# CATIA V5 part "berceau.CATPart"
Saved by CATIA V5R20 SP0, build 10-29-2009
Part number: berceau
Bounding box of the stored display mesh (mm): x -325 to 325, y -1050 to -50, z 1210.026 to 1425
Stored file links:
  D:\Dropbox\Pack 1 sylvain\mmoreau\mmoreau\mmoreau\fin\berceau.CATPart
  U:\think motion\fin\think motion2.CATProduct
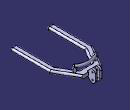
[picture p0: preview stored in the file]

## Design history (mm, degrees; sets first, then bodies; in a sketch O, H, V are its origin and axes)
External parameters (linked from other documents)
  `External.largeur levier` = 40 mm
Set1
  Plane1: linked copy from another document
  Plane2: linked copy from another document
  Point1: linked copy from another document
  Plane3: linked copy from another document
  Point2: linked copy from another document
Set2
  Plane4: type Normal, Curve Sketch3, RefPoint Sketch3.P2
  Plane5: type Normal, Curve Sketch5, RefPoint Sketch5.P2
Body1 (main body)
  Sketch1 on Plane1, origin (0, 0, 1300), H (1, 0, 0), V (0, 1, 0)
    line L1 (-150, -150) -> (150, -150)
    line L2 (325, -453.1089) -> (325, -1050)
    line L3 (-225, -1050) -> (-325, -1050)
    line L4 (-325, -1050) -> (-325, -453.1089)
    point P1 (-325, -1050)
    line L5 (150, -150) -> (325, -453.1089)
    point P3 (325, -453.1089)
    point P4 (-325, -453.1089)
    line L6 (-150, -150) -> (-325, -453.1089)
    line L7 (-225, -1050) -> (-225, -479.9038)
    point P6 (-225, -1050)
    point P7 (-225, -479.9038)
    line L8 (-225, -479.9038) -> (-92.265, -250)
    point P8 (-92.265, -250)
    line L9 (-92.265, -250) -> (0, -250)
    point P9 (-92.265, -250)
    point P10 (0, -250)
    point P11 (225, -479.9038)
    point P12 (225, -1050)
    line L10 (225, -1050) -> (225, -479.9038)
    point P13 (92.265, -250)
    line L11 (225, -479.9038) -> (92.265, -250)
    point P14 (0, -250)
    point P15 (92.265, -250)
    line L12 (92.265, -250) -> (0, -250)
    point P16 (325, -1050)
    line L13 (225, -1050) -> (325, -1050)
    reference intersected line E1 through (0, -150) direction (1, 0) from Plane3
    distance L2 L4 = 650
    distance L7 L4 = 100
    distance L8 L6 = 100
    distance L9 L1 = 100
    angle L6 L1 = 120
    length L1 = 300
    distance L3 L9 = 800
    horizontal: L1 H, L3 H, L9 H
    vertical: L2 V, L4 V, L7 V
    symmetry: L4 L2 V, P3 P4 V, L5 L6 V, P7 P11 V, P6 P12 V, L7 L10 V, P8 P13 V, L8 L11 V, P10 P14 V, P9 P15 V, L9 L12 V, P1 P16 V, L3 L13 V
    coincidence: P9 L8, P10 V, P8 P9, E1 L1
  Pad1: profile Sketch1, direction (0, 0, 1), length 25, mirrored extent
  Sketch2 on Plane4, origin (224.3751, -208.243, 0), H (-0.6803, -0.733, 0), V (0, 0, 1)
    line L1 (59.8343, 1425) -> (99.8343, 1425)
    line L2 (99.8343, 1425) -> (99.8343, 1325)
    line L3 (99.8343, 1325) -> (59.8343, 1325)
    line L4 (59.8343, 1325) -> (59.8343, 1425)
    point P4 (59.8343, 1325)
    reference projected point E1 (59.8343, 1325) from Sketch3.P2
    distance L2 L4 = 40
    distance L3 L1 = 100
    horizontal: L1 H, L3 H
    vertical: L2 V, L4 V
    coincidence: P4 E1
  Sketch3 on end face of Pad1, origin (0, 0, 1325), H (1, 0, 0), V (0, 1, 0)
    arc A1 centre (0, -450) radius 270 from (183.6719, -252.0994) to (-183.6719, -252.0994) ccw
    point P1 (0, -450)
    point P2 (183.6719, -252.0994)
    point P3 (-183.6719, -252.0994)
    reference projected point E1 (0, -150) from Point2
    distance P2 P3 V = 0
    radius A1 = 270
    distance E1 P1 = 300
    coincidence: P1 V
  Rib1: profile Sketch2, centre curve Sketch3
  Fillet1: radius 20, on edge [face of Rib1 | face of Rib1] (x6)
  Fillet2: radius 20, on edge [face of Fillet1 | face of Fillet1] (x2)
  Sketch4 on Plane5, origin (210.6842, -141.9392, 0), H (-0.5645, -0.8254, 0), V (0, 0, 1)
    line L1 (103.2148, 1385) -> (143.2148, 1385)
    line L2 (143.2148, 1385) -> (143.2148, 1325)
    line L3 (143.2148, 1325) -> (103.2148, 1325)
    line L4 (103.2148, 1325) -> (103.2148, 1385)
    point P4 (103.2148, 1325)
    reference projected point E1 (103.2148, 1325) from Sketch5.P2
    distance L4 L2 = 40
    distance L3 L1 = 60
    horizontal: L1 H, L3 H
    vertical: L2 V, L4 V
    coincidence: P4 E1
  Sketch5 on end face of Pad1, origin (0, 0, 1325), H (1, 0, 0), V (0, 1, 0)
    arc A1 centre (0, -450) radius 270 from (152.4182, -227.1353) to (-152.4182, -227.1353) ccw
    point P1 (0, -450)
    point P2 (152.4182, -227.1353)
    point P3 (-152.4182, -227.1353)
    reference projected arc E1 centre (0, -450) radius 270 from (183.6719, -252.0994) to (-183.6719, -252.0994) ccw from Sketch3.A1
    reference projected arc E2 centre (0, -450) radius 270 from (183.6719, -252.0994) to (-183.6719, -252.0994) ccw from Sketch3.A1
    reference projected point E3 (183.6719, -252.0994) from vertex [element of Sketch2 | element of Sketch2]
    distance P2 P3 V = 0
    distance E3 P2 = 40
    coincidence: P1 V, A1 E2
    concentricity: A1 E1
  Slot1: profile Sketch4, centre curve Sketch5
  Fillet3: radius 20, on edge [face of Slot1 | face of Rib1]; edge [face of Rib1 | face of Slot1]
  Fillet4: radius 18, on edge [face of Rib1 | face of Slot1] (x4)
  Fillet5: radius 18, on edge [face of Slot1 | face of Fillet3] (x2)
  Fillet6: radius 25, on edge [face of Pad1 from Sketch1.L10 | face of Slot1]; edge [start face of Pad1 | face of Pad1 from Sketch1.L10]; edge [face of Pad1 from Sketch1.L11 | face of Slot1]; edge [face of Pad1 from Sketch1.L8 | face of Slot1]; edge [face of Pad1 from Sketch1.L7 | face of Slot1]; edge [start face of Pad1 | face of Pad1 from Sketch1.L11]; edge [start face of Pad1 | face of Pad1 from Sketch1.L12]; edge [start face of Pad1 | face of Pad1 from Sketch1.L8]; edge [start face of Pad1 | face of Pad1 from Sketch1.L7]; edge [face of Pad1 from Sketch1.L12 | face of Slot1]; edge [face of Pad1 from Sketch1.L2 | face of Slot1]; edge [start face of Pad1 | face of Pad1 from Sketch1.L2]; edge [face of Pad1 from Sketch1.L5 | face of Slot1]; edge [start face of Pad1 | face of Pad1 from Sketch1.L5]; edge [face of Pad1 from Sketch1.L4 | face of Slot1]; edge [start face of Pad1 | face of Pad1 from Sketch1.L4]; edge [face of Pad1 from Sketch1.L6 | face of Slot1]; edge [start face of Pad1 | face of Pad1 from Sketch1.L6]
  Fillet7: radius 25, on face of Pad1 from Sketch1.L13; face of Pad1 from Sketch1.L3
  Sketch6 on Plane2, origin (0, 0, 0), H (0, 1, 0), V (0, 0, 1)
    line L1 (-171.5685, 1325) -> (-118.2843, 1378.2843)
    point P1 (-171.5685, 1325)
    point P2 (-50, 1446.5685)
    line L2 (-50, 1350) -> (-50, 1250)
    point P3 (-50, 1446.5685)
    point P4 (-50, 1153.4315)
    line L3 (-118.2843, 1221.7157) -> (-171.5685, 1275)
    point P5 (-171.5685, 1275)
    reference projected line E1 (-150, 1325) -> (-459.8076, 1325) from edge [face of Fillet6 | face of Slot1]
    reference projected line E2 (-459.8076, 1275) -> (-150, 1275) from edge [start face of Pad1 | face of Fillet6]
    reference projected line E3 (-453.1089, 1300) -> (-150, 1300) from edge [face of Fillet6 | face of Fillet6]
    arc A1 centre (-90, 1350) radius 40 from (-118.2843, 1378.2843) to (-50, 1350) cw
    point P8 (-90, 1350)
    arc A2 centre (-90, 1250) radius 40 from (-118.2843, 1221.7157) to (-50, 1250) ccw
    line L4 (-171.5685, 1325) -> (-171.5685, 1275)
    point P12 (-171.5685, 1275)
    circle A3 centre (-90, 1350) radius 10
    point P13 (-90, 1350)
    circle A4 centre (-90, 1250) radius 10
    reference projected point E4 (-90, 1350) from Point1
    distance P5 P1 H = 0
    radius A1 = 40
    radius A2 = 40
    radius A3 = 10
    radius A4 = 10
    coincidence: P3 L1, P2 P3, P1 E1, P5 E2, L1 P2, L2 P3, L3 P4, L2 P4, P12 L3, P13 P8, P12 P5, E4 P13
    vertical: L2 V
    perpendicularity: L3 L1
    symmetry: P4 P2 E3
    tangency: A1 L1, A1 L2, A2 L3, A2 L2
  Pad2: profile Sketch6, direction (1, 0, 0), length 50, mirrored extent
  Sketch7 on face of Pad2 from Sketch6.L2, origin (0, -50, 0), H (-1, 0, 0), V (0, 0, 1)
    line L1 (-20, 1491.3628) -> (20, 1491.3628)
    line L2 (20, 1491.3628) -> (20, 1201.1926)
    line L3 (20, 1201.1926) -> (-20, 1201.1926)
    line L4 (-20, 1201.1926) -> (-20, 1491.3628)
    reference intersected line E1 through (0, 0) direction (0, -1) from Plane2
    distance L2 L4 = 40 {= `External.largeur levier`}
    horizontal: L1 H, L3 H
    vertical: L2 V, L4 V
    symmetry: L2 L4 E1
  Pocket1: profile Sketch7, direction (0, -1, 0), length 70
